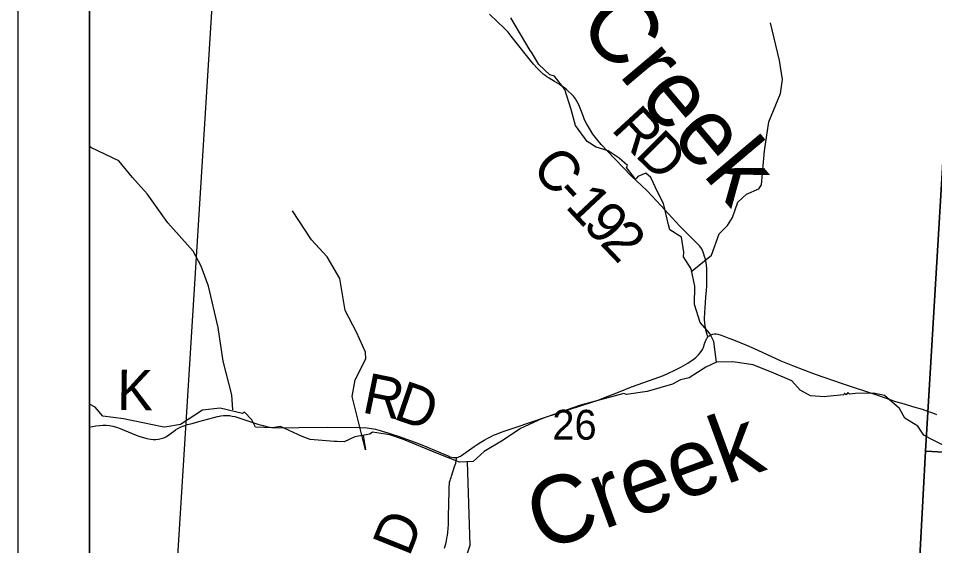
# Model space of a CAD drawing. Extents: x 0 to 34, y 0 to 22.
# Drawn here: x 23.737 to 25.024, y 15.745 to 16.486 of the extents above; entities that cross this region are included whole.
import ezdxf

# ---------------------------------------------------------------- set-up
doc = ezdxf.new("R2010")
doc.units = 0
for name, color, linetype in [('GM_X_County_Road', 7, 'Continuous'), ('GM_X_County_Road_Text', 7, 'Continuous'), ('GM_X_County_Text', 7, 'Continuous'), ('GM_X_Minor_River', 7, 'Continuous'), ('GM_X_Minor_River_Text', 7, 'Continuous'), ('GM_X_Section', 7, 'Continuous'), ('GM_X_Section_Text', 7, 'Continuous'), ('GM_X_Township_Road', 7, 'Continuous'), ('GM_X_Township_Road_Text', 7, 'Continuous'), ('SH_Cut_Line', 7, 'Continuous'), ('SH_Data', 7, 'Continuous')]:
    doc.layers.add(name, color=color, linetype=linetype)

msp = doc.modelspace()

# ---------------------------------------------------------------- linework, layer by layer
at = {"layer": 'GM_X_County_Road'}
for points in [[(24.7058, 16.0383), (24.7043, 16.043), (24.7029, 16.0477), (24.7022, 16.0505), (24.7017, 16.0536), (24.7012, 16.058), (24.7011, 16.0619), (24.7011, 16.0662), (24.7012, 16.0699), (24.7014, 16.0735), (24.7019, 16.0791), (24.703, 16.0937), (24.7039, 16.1037), (24.7041, 16.1095), (24.7042, 16.1171), (24.7043, 16.1247), (24.7042, 16.1297), (24.704, 16.1341), (24.7037, 16.1384), (24.7031, 16.1428), (24.7022, 16.1471), (24.7011, 16.1511), (24.7001, 16.1545), (24.6992, 16.1573), (24.6983, 16.1596), (24.697, 16.1618), (24.6955, 16.164), (24.694, 16.166), (24.6922, 16.1679), (24.6858, 16.1741), (24.6657, 16.1941), (24.6402, 16.2223), (24.6332, 16.2298), (24.627, 16.2362), (24.6202, 16.2432), (24.6125, 16.2507), (24.598, 16.2642), (24.5642, 16.2994), (24.5559, 16.3085), (24.5497, 16.3158), (24.5442, 16.323), (24.5393, 16.3306), (24.5358, 16.3367), (24.5326, 16.3429), (24.5303, 16.3486), (24.5261, 16.3595), (24.5242, 16.3641), (24.5222, 16.3685), (24.5199, 16.3723), (24.517, 16.3761), (24.5136, 16.3796), (24.5096, 16.3834), (24.5067, 16.3859), (24.5041, 16.388), (24.5006, 16.3905), (24.4967, 16.393), (24.4933, 16.3951), (24.4903, 16.3969), (24.4828, 16.4014), (24.4797, 16.4034), (24.4772, 16.4051), (24.4744, 16.4073), (24.4706, 16.4109), (24.4656, 16.4158), (24.4607, 16.4213), (24.4567, 16.4261), (24.4528, 16.4308), (24.4385, 16.4491), (24.4293, 16.4606), (24.425, 16.4659), (24.4221, 16.4692), (24.4191, 16.4723), (24.4108, 16.4804), (24.3988, 16.4914)], [(24.2482, 15.9058), (24.256, 15.9035), (24.2619, 15.9017), (24.2708, 15.8988), (24.2889, 15.8923), (24.3039, 15.8865), (24.3218, 15.8788), (24.3417, 15.8704), (24.3434, 15.8697), (24.3455, 15.8691), (24.3477, 15.8687), (24.3502, 15.8685), (24.3529, 15.8687), (24.3549, 15.8691), (24.3567, 15.87), (24.3582, 15.8707), (24.3597, 15.8717), (24.3775, 15.8842), (24.3818, 15.887), (24.3869, 15.8904), (24.3916, 15.8932), (24.3965, 15.8959), (24.4012, 15.8983), (24.4048, 15.9), (24.4088, 15.9017), (24.4167, 15.9049), (24.4362, 15.9114), (24.4774, 15.9254), (24.544, 15.9468), (24.5503, 15.949), (24.5571, 15.9515), (24.5803, 15.9604), (24.5984, 15.9678), (24.6236, 15.9768), (24.6435, 15.9841), (24.6504, 15.9871), (24.6582, 15.991), (24.6675, 15.9956), (24.6776, 16.0014), (24.681, 16.0034), (24.6845, 16.0058), (24.6888, 16.0093), (24.6927, 16.013), (24.6963, 16.0174), (24.6982, 16.0203), (24.6992, 16.0225), (24.6998, 16.0244), (24.7006, 16.0269), (24.7014, 16.0296), (24.7022, 16.032), (24.7031, 16.0342), (24.7043, 16.0365), (24.705, 16.0374), (24.7058, 16.0383), (24.7066, 16.039), (24.7076, 16.0398), (24.7099, 16.041), (24.7126, 16.0418), (24.7149, 16.0422), (24.7172, 16.0422), (24.7198, 16.0418), (24.723, 16.041), (24.7283, 16.0393), (24.7352, 16.0365), (24.7415, 16.034), (24.7599, 16.0264), (24.7707, 16.0219), (24.7942, 16.011), (24.8079, 16.0046), (24.8243, 15.9978), (24.8388, 15.9921), (24.8563, 15.9857), (24.8945, 15.9726), (24.9452, 15.9556), (24.9694, 15.9476), (24.9812, 15.9439), (24.9932, 15.9404), (25.0066, 15.9365), (25.0142, 15.9339), (25.021, 15.9314), (25.0266, 15.9289)], [(23.8372, 15.9111), (23.8414, 15.9122), (23.8462, 15.9132), (23.8512, 15.9139), (23.8561, 15.9142), (23.8607, 15.9141), (23.8651, 15.9137), (23.8698, 15.9127), (23.875, 15.9112), (23.8801, 15.9094), (23.9027, 15.9001), (23.9077, 15.8984), (23.9131, 15.8967), (23.9178, 15.8955), (23.9229, 15.8944), (23.9267, 15.894), (23.9305, 15.894), (23.9342, 15.8944), (23.9379, 15.8953), (23.9415, 15.8965), (23.9443, 15.8979), (23.9496, 15.9012), (23.9524, 15.9033), (23.9551, 15.9054), (23.9581, 15.9075), (23.9612, 15.9093), (23.9646, 15.9111), (23.9696, 15.9132), (23.9748, 15.915), (23.9813, 15.9167), (23.9905, 15.9191), (24.0116, 15.925), (24.0169, 15.9265), (24.0214, 15.9273), (24.0255, 15.9277), (24.0298, 15.9278), (24.0338, 15.9275), (24.0375, 15.927), (24.0411, 15.9262), (24.0555, 15.9216), (24.0735, 15.9157), (24.081, 15.9135), (24.0874, 15.9119), (24.0933, 15.911), (24.0991, 15.9107), (24.1045, 15.9105), (24.1311, 15.9109), (24.1715, 15.9112), (24.2179, 15.9108), (24.2271, 15.9102), (24.2333, 15.9095), (24.2387, 15.9084), (24.2453, 15.9067), (24.2482, 15.9058)]]:
    msp.add_lwpolyline(points, dxfattribs=at)
at = {"layer": 'GM_X_County_Text'}
msp.add_lwpolyline([(23.8372, 20.6485), (23.8372, 14.4177), (24.4263, 14.3937), (25.7269, 14.3414), (26.0929, 14.3266), (26.1939, 14.3226), (26.568, 14.3076), (26.7502, 14.2997), (27.0716, 14.2873), (27.1862, 14.3829)], dxfattribs=at)
at = {"layer": 'GM_X_Minor_River'}
for points in [[(24.718, 16.0025), (24.7138, 16.0317), (24.7085, 16.0431), (24.6949, 16.0583), (24.6869, 16.0837), (24.6873, 16.1092), (24.6823, 16.1339), (24.6714, 16.1506), (24.6721, 16.157), (24.6687, 16.1783), (24.6524, 16.1885), (24.6505, 16.1954), (24.6433, 16.2254), (24.635, 16.2417), (24.6255, 16.2622), (24.6187, 16.2679), (24.6074, 16.2633), (24.6059, 16.2614), (24.604, 16.2595), (24.5915, 16.2762), (24.5926, 16.2789), (24.5809, 16.2891), (24.5658, 16.2993), (24.5487, 16.3046), (24.5363, 16.3125), (24.5196, 16.3349), (24.5135, 16.3573), (24.5048, 16.3854), (24.4901, 16.4044), (24.4836, 16.4063), (24.4681, 16.4207), (24.4579, 16.4382), (24.456, 16.4404), (24.4288, 16.4864)], [(24.6834, 16.1308), (24.7106, 16.1531), (24.7213, 16.1831), (24.7334, 16.1945), (24.7401, 16.2057), (24.7476, 16.2275), (24.76, 16.2388), (24.7773, 16.2463), (24.7808, 16.2518), (24.7853, 16.2995), (24.7915, 16.3403), (24.8078, 16.3801), (24.8103, 16.3997), (24.8062, 16.4264), (24.7934, 16.4792)], [(24.0386, 15.9358), (24.0369, 15.9567), (24.0248, 16.0038), (24.0179, 16.0515), (24.0045, 16.1092), (23.994, 16.1376), (23.9826, 16.1585), (23.9471, 16.1984), (23.9181, 16.2392), (23.8977, 16.2618), (23.8783, 16.2852), (23.8399, 16.3036), (23.8372, 16.3065)], [(24.2215, 15.8999), (24.2249, 15.8797), (24.2061, 15.9545), (24.2102, 15.9777), (24.2253, 16.0073), (24.2249, 16.0168), (24.212, 16.0449), (24.1964, 16.0753), (24.1887, 16.1201), (24.1711, 16.1505), (24.1491, 16.1744), (24.1221, 16.2153)], [(24.8355, 15.9632), (24.8235, 15.9765), (24.7985, 15.9871), (24.7694, 15.9988), (24.7407, 16.0033), (24.718, 16.0025), (24.7029, 15.9956), (24.6795, 15.9804), (24.6674, 15.978), (24.656, 15.9719), (24.6205, 15.9616), (24.5914, 15.9573), (24.5876, 15.9585), (24.5268, 15.942), (24.472, 15.9232), (24.4425, 15.9095), (24.418, 15.8931), (24.3915, 15.8771), (24.376, 15.863), (24.3567, 15.8622), (24.3257, 15.8743), (24.2781, 15.8939), (24.2592, 15.9007), (24.2346, 15.9041), (24.2308, 15.9014), (24.21, 15.8979), (24.1949, 15.8907), (24.1851, 15.891), (24.1809, 15.891), (24.1469, 15.894), (24.1359, 15.8981), (24.1053, 15.9121), (24.094, 15.9106), (24.0705, 15.9113), (24.0652, 15.9215), (24.055, 15.9322), (24.052, 15.9306)], [(25.058, 15.8752), (25.0182, 15.8949), (25.0092, 15.9002), (25.0005, 15.9127), (24.9823, 15.9241), (24.9747, 15.9377), (24.9539, 15.9559), (24.9384, 15.9593), (24.9131, 15.9585), (24.9044, 15.9577), (24.9021, 15.96), (24.8999, 15.9569), (24.8976, 15.9592), (24.8965, 15.9569), (24.8727, 15.9546), (24.8696, 15.9538), (24.85, 15.9553), (24.8354, 15.9633)], [(24.052, 15.9306), (24.0206, 15.9378), (23.996, 15.9351), (23.9651, 15.9149), (23.9431, 15.9114), (23.939, 15.9118), (23.8849, 15.923), (23.8558, 15.9268), (23.8452, 15.9393), (23.8372, 15.9434)], [(24.3676, 15.8626), (24.3712, 15.7451), (24.3612, 15.7147)]]:
    msp.add_lwpolyline(points, dxfattribs=at)
at = {"layer": 'GM_X_Section'}
for points in [[(24.5596, 16.5135), (25.0459, 16.4982), (25.0486, 16.498), (25.0369, 16.3074), (25.0112, 15.8778), (24.9883, 15.4512), (23.9474, 15.5054), (24.0115, 16.5331)], [(25.0369, 16.3074), (26.067, 16.2576), (26.0395, 15.8225), (25.0112, 15.8778)], [(26.0395, 15.8225), (26.0137, 15.3999), (24.9883, 15.4512), (25.0112, 15.8778)]]:
    msp.add_lwpolyline(points, close=True, dxfattribs=at)
at = {"layer": 'GM_X_Township_Road'}
msp.add_lwpolyline([(24.3358, 15.7416), (24.3376, 15.7475), (24.3385, 15.7516), (24.3392, 15.7555), (24.3398, 15.759), (24.3404, 15.7634), (24.341, 15.7692), (24.3414, 15.7748), (24.3416, 15.7877), (24.3419, 15.8013), (24.3421, 15.8243), (24.3423, 15.8279), (24.3426, 15.8314), (24.343, 15.8342), (24.3435, 15.8365), (24.3441, 15.8385), (24.345, 15.8406), (24.3456, 15.8423), (24.35, 15.8563), (24.3515, 15.8608), (24.3523, 15.8646), (24.3529, 15.8687)], dxfattribs=at)
at = {"layer": 'SH_Cut_Line'}
msp.add_lwpolyline([(23.8372, 20.9), (23.8372, 14.4177), (24.4263, 14.3937), (25.7269, 14.3414), (26.0929, 14.3266), (26.1939, 14.3226), (26.568, 14.3076), (26.7502, 14.2997), (27.0716, 14.2873), (27.1862, 14.3829)], dxfattribs=at)
at = {"layer": 'SH_Data'}
for points in [[(23.7372, 21), (30.7372, 21), (30.7372, 14), (23.7372, 14)], [(23.8372, 20.9), (30.6372, 20.9), (30.6372, 14.1), (23.8372, 14.1)]]:
    msp.add_lwpolyline(points, close=True, dxfattribs=at)

# ---------------------------------------------------------------- texts
at = {"layer": 'GM_X_County_Road_Text'}
for s, rotation, p in [('R', 312.6728, (24.5686, 16.3291)), ('D', 315.1012, (24.602, 16.293)), ('C', 311.4154, (24.4561, 16.2741)), ('-', 312.6481, (24.4879, 16.2381)), ('1', 313.1524, (24.5041, 16.2206)), ('9', 313.6665, (24.5284, 16.1946)), ('2', 313.7988, (24.5527, 16.1692)), ('K', 359.1294, (23.8755, 15.9356)), ('R', 348.4513, (24.2183, 15.9324)), ('D', 341.0259, (24.2622, 15.9236))]:
    msp.add_text(s, height=0.0568, rotation=rotation, dxfattribs=at).set_placement(p)
at = {"layer": 'GM_X_Minor_River_Text'}
for rotation, p in [(310.1368, (24.5206, 16.4758)), (20.1308, (24.473, 15.7358))]:
    msp.add_text('Creek', height=0.09469, rotation=rotation, dxfattribs=at).set_placement(p)
at = {"layer": 'GM_X_Section_Text'}
msp.add_text('26', height=0.04186, rotation=0, dxfattribs=at).set_placement((24.4872, 15.8938))
at = {"layer": 'GM_X_Township_Road_Text'}
msp.add_text('D', height=0.0568, rotation=68.2671, dxfattribs=at).set_placement((24.286, 15.7281))

doc.saveas('drawing.dxf')
